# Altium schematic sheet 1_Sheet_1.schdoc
size 497 x 243 mm; Name: A_A4; Symbol: A_A4; Device: A_A4; @Project Name: Sheet_1; REV: 1.0; Date: 2023-03-21; Sheet: 1/1; Draw By: PKKKK; Company: Your Company; Convert to PCB: yes; Add into BOM: yes
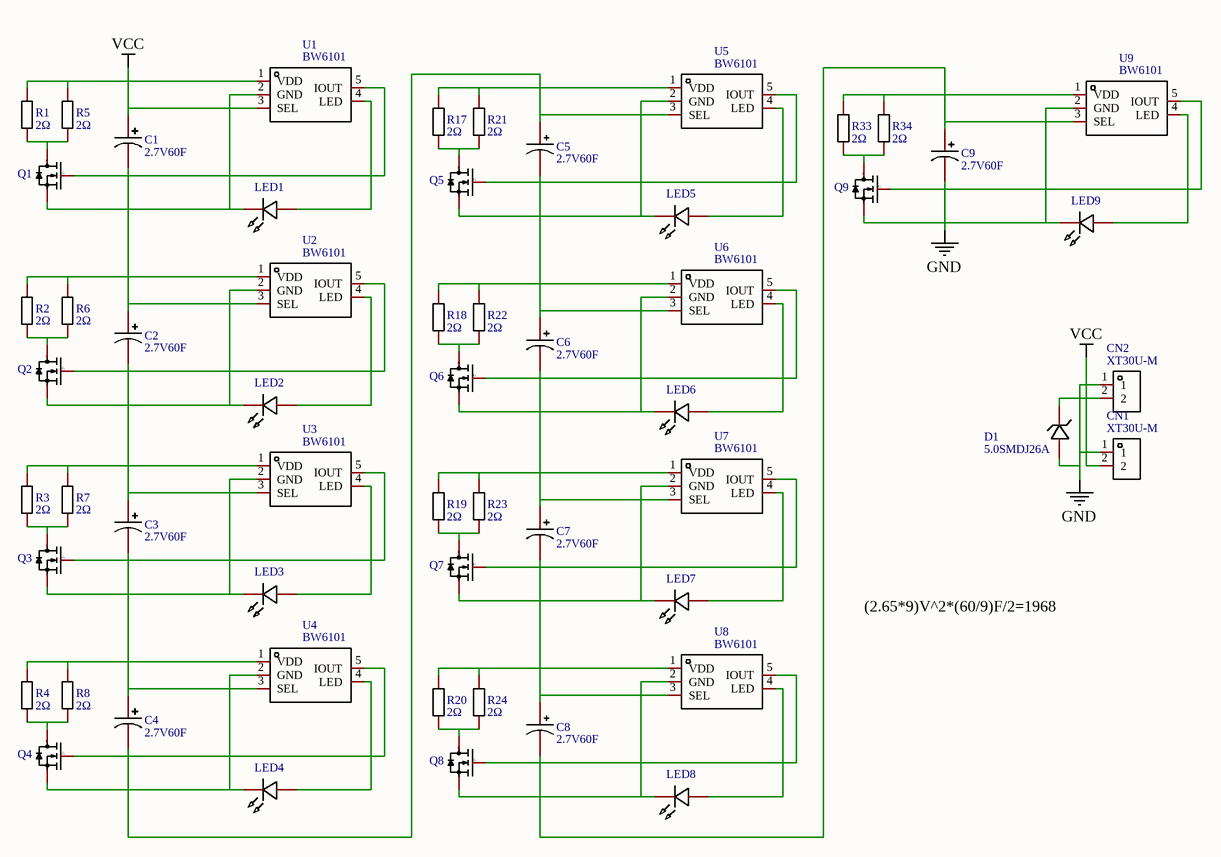
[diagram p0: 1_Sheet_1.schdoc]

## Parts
C1  2.7V60F  [CAP-TH_BD18.0-P7.70-D0.8-FD]
C2  2.7V60F  [CAP-TH_BD18.0-P7.70-D0.8-FD]
C3  2.7V60F  [CAP-TH_BD18.0-P7.70-D0.8-FD]
C4  2.7V60F  [CAP-TH_BD18.0-P7.70-D0.8-FD]
C5  2.7V60F  [CAP-TH_BD18.0-P7.70-D0.8-FD]
C6  2.7V60F  [CAP-TH_BD18.0-P7.70-D0.8-FD]
C7  2.7V60F  [CAP-TH_BD18.0-P7.70-D0.8-FD]
C8  2.7V60F  [CAP-TH_BD18.0-P7.70-D0.8-FD]
C9  2.7V60F  [CAP-TH_BD18.0-P7.70-D0.8-FD]
CN1  XT30U-M  [CONN-TH_XT30U-M]
CN2  XT30U-M  [CONN-TH_XT30U-M]
D1  5.0SMDJ26A  [SMC_L6.9-W5.9-LS7.9-RD]
LED1  LED-0603_R  [LED0603_RED]  (value not drawn)
LED2  LED-0603_R  [LED0603_RED]  (value not drawn)
LED3  LED-0603_R  [LED0603_RED]  (value not drawn)
LED4  LED-0603_R  [LED0603_RED]  (value not drawn)
LED5  LED-0603_R  [LED0603_RED]  (value not drawn)
LED6  LED-0603_R  [LED0603_RED]  (value not drawn)
LED7  LED-0603_R  [LED0603_RED]  (value not drawn)
LED8  LED-0603_R  [LED0603_RED]  (value not drawn)
LED9  LED-0603_R  [LED0603_RED]  (value not drawn)
Q1  AO3400_C181090  [SOT-23-3_L2.9-W1.3-P1.90-LS2.4-BR]  (value not drawn)
Q2  AO3400_C181090  [SOT-23-3_L2.9-W1.3-P1.90-LS2.4-BR]  (value not drawn)
Q3  AO3400_C181090  [SOT-23-3_L2.9-W1.3-P1.90-LS2.4-BR]  (value not drawn)
Q4  AO3400_C181090  [SOT-23-3_L2.9-W1.3-P1.90-LS2.4-BR]  (value not drawn)
Q5  AO3400_C181090  [SOT-23-3_L2.9-W1.3-P1.90-LS2.4-BR]  (value not drawn)
Q6  AO3400_C181090  [SOT-23-3_L2.9-W1.3-P1.90-LS2.4-BR]  (value not drawn)
Q7  AO3400_C181090  [SOT-23-3_L2.9-W1.3-P1.90-LS2.4-BR]  (value not drawn)
Q8  AO3400_C181090  [SOT-23-3_L2.9-W1.3-P1.90-LS2.4-BR]  (value not drawn)
Q9  AO3400_C181090  [SOT-23-3_L2.9-W1.3-P1.90-LS2.4-BR]  (value not drawn)
R1  2Ω  [R2512]
R2  2Ω  [R2512]
R3  2Ω  [R2512]
R4  2Ω  [R2512]
R5  2Ω  [R2512]
R6  2Ω  [R2512]
R7  2Ω  [R2512]
R8  2Ω  [R2512]
R17  2Ω  [R2512]
R18  2Ω  [R2512]
R19  2Ω  [R2512]
R20  2Ω  [R2512]
R21  2Ω  [R2512]
R22  2Ω  [R2512]
R23  2Ω  [R2512]
R24  2Ω  [R2512]
R33  2Ω  [R2512]
R34  2Ω  [R2512]
U1  BW6101  [SOT-23-5_L2.9-W1.6-P0.95-LS2.8-BL]
U2  BW6101  [SOT-23-5_L2.9-W1.6-P0.95-LS2.8-BL]
U3  BW6101  [SOT-23-5_L2.9-W1.6-P0.95-LS2.8-BL]
U4  BW6101  [SOT-23-5_L2.9-W1.6-P0.95-LS2.8-BL]
U5  BW6101  [SOT-23-5_L2.9-W1.6-P0.95-LS2.8-BL]
U6  BW6101  [SOT-23-5_L2.9-W1.6-P0.95-LS2.8-BL]
U7  BW6101  [SOT-23-5_L2.9-W1.6-P0.95-LS2.8-BL]
U8  BW6101  [SOT-23-5_L2.9-W1.6-P0.95-LS2.8-BL]
U9  BW6101  [SOT-23-5_L2.9-W1.6-P0.95-LS2.8-BL]

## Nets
GND: C9.2 CN1.1 CN2.1 D1.2(A) LED9.2 Q9.2(S) U9.2(GND)
VCC: C1.1 CN1.2 CN2.2 D1.1(C) R1.2 R5.2 U1.1(VDD) U1.3(SEL)
NetC1_2: C1.2 C2.1 LED1.2 Q1.2(S) R2.2 R6.2 U1.2(GND) U2.1(VDD) U2.3(SEL)
NetC2_2: C2.2 C3.1 LED2.2 Q2.2(S) R3.2 R7.2 U2.2(GND) U3.1(VDD) U3.3(SEL)
NetC3_2: C3.2 C4.1 LED3.2 Q3.2(S) R4.2 R8.2 U3.2(GND) U4.1(VDD) U4.3(SEL)
NetC4_2: C4.2 C5.1 LED4.2 Q4.2(S) R17.2 R21.2 U4.2(GND) U5.1(VDD) U5.3(SEL)
NetC5_2: C5.2 C6.1 LED5.2 Q5.2(S) R18.2 R22.2 U5.2(GND) U6.1(VDD) U6.3(SEL)
NetC6_2: C6.2 C7.1 LED6.2 Q6.2(S) R19.2 R23.2 U6.2(GND) U7.1(VDD) U7.3(SEL)
NetC7_2: C7.2 C8.1 LED7.2 Q7.2(S) R20.2 R24.2 U7.2(GND) U8.1(VDD) U8.3(SEL)
NetC8_2: C8.2 C9.1 LED8.2 Q8.2(S) R33.2 R34.2 U8.2(GND) U9.1(VDD) U9.3(SEL)
NetLED1_1: LED1.1 U1.4(LED)
NetLED2_1: LED2.1 U2.4(LED)
NetLED3_1: LED3.1 U3.4(LED)
NetLED4_1: LED4.1 U4.4(LED)
NetLED5_1: LED5.1 U5.4(LED)
NetLED6_1: LED6.1 U6.4(LED)
NetLED7_1: LED7.1 U7.4(LED)
NetLED8_1: LED8.1 U8.4(LED)
NetLED9_1: LED9.1 U9.4(LED)
NetQ1_1: Q1.1(G) U1.5(IOUT)
NetQ1_3: Q1.3(D) R1.1 R5.1
NetQ2_1: Q2.1(G) U2.5(IOUT)
NetQ2_3: Q2.3(D) R2.1 R6.1
NetQ3_1: Q3.1(G) U3.5(IOUT)
NetQ3_3: Q3.3(D) R3.1 R7.1
NetQ4_1: Q4.1(G) U4.5(IOUT)
NetQ4_3: Q4.3(D) R4.1 R8.1
NetQ5_1: Q5.1(G) U5.5(IOUT)
NetQ5_3: Q5.3(D) R17.1 R21.1
NetQ6_1: Q6.1(G) U6.5(IOUT)
NetQ6_3: Q6.3(D) R18.1 R22.1
NetQ7_1: Q7.1(G) U7.5(IOUT)
NetQ7_3: Q7.3(D) R19.1 R23.1
NetQ8_1: Q8.1(G) U8.5(IOUT)
NetQ8_3: Q8.3(D) R20.1 R24.1
NetQ9_1: Q9.1(G) U9.5(IOUT)
NetQ9_3: Q9.3(D) R33.1 R34.1

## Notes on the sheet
- (2.65*9)V^2*(60/9)F/2=1968

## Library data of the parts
C1-C9 = 2.7V60F: Manufacturer: CDA(智烽维); Manufacturer Part: CHV-2R7606R-TW 2.7V60F; Capacitance: 60F; Add into BOM: yes
CN1 CN2 = XT30U-M: Manufacturer: AMASS(艾迈斯); Add into BOM: yes
D1 = 5.0SMDJ26A: Manufacturer: BORN(伯恩半导体); Add into BOM: yes
LED1-LED9 = LED-0603_R: Manufacturer: EVERLIGHT(台湾亿光); Manufacturer Part: 19-217/R6C-AL1M2VY/3T; Add into BOM: yes
Q1-Q9 = AO3400_C181090: Manufacturer: Hottech(合科泰); Manufacturer Part: AO3400; 3DModel: SOT-23-3P_L2.9-W1.3-H1.0-LS2.4-P0.95; libConvert: Yes
R1-R8 R17-R24 R33 R34 = 2Ω: Manufacturer: UNI-ROYAL(厚声); Manufacturer Part: HP122WF200KT4E; 3DModel: R2512_L6.3-W3.2-H0.6; Resistance: 2; Add into BOM: yes
U1-U9 = BW6101: Manufacturer: null; Add into BOM: yes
